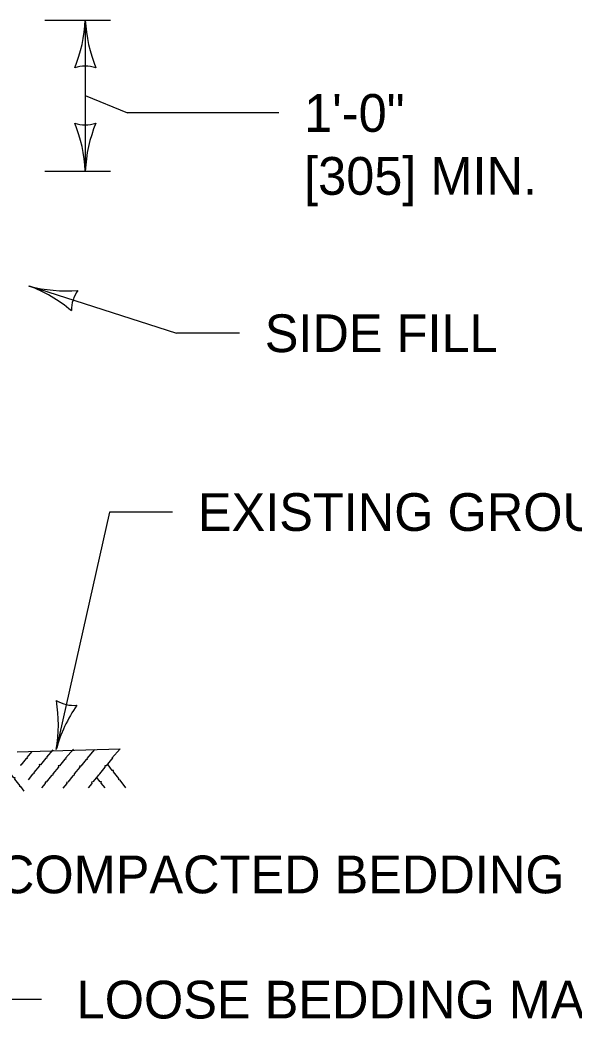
# Model space of a CAD drawing. Extents: x 49991.4 to 50021, y 49987.6 to 50011.4.
# Drawn here: x 50005.577 to 50006.457, y 49992.853 to 49994.441 of the extents above; entities that cross this region are included whole.
import ezdxf

# ---------------------------------------------------------------- set-up
doc = ezdxf.new("R2010")
doc.units = 0
for name, color, linetype in [('Level 1', 7, 'Continuous'), ('Level 2', 7, 'Continuous'), ('Level 3', 7, 'Continuous')]:
    doc.layers.add(name, color=color, linetype=linetype)

msp = doc.modelspace()

# ---------------------------------------------------------------- linework, layer by layer
at = {"layer": 'Level 1'}
msp.add_line((50005.5724, 49993.2778), (50005.7362, 49993.2827), dxfattribs=at)
for points in [[(50005.5959, 49993.2783), (50005.5877, 49993.2687), (50005.5885, 49993.2671), (50005.5869, 49993.2671), (50005.5784, 49993.2566), (50005.5773, 49993.2567)], [(50005.6291, 49993.281), (50005.6191, 49993.2694), (50005.6199, 49993.2678), (50005.6183, 49993.2678), (50005.6098, 49993.2573), (50005.6077, 49993.2574), (50005.6079, 49993.2553), (50005.5991, 49993.2448), (50005.5991, 49993.2427), (50005.5972, 49993.2421), (50005.5903, 49993.2334)], [(50005.6619, 49993.2822), (50005.6492, 49993.2674), (50005.65, 49993.2658), (50005.6484, 49993.2658), (50005.6399, 49993.2554), (50005.6377, 49993.2554), (50005.638, 49993.2534), (50005.6292, 49993.2428), (50005.6292, 49993.2407), (50005.6273, 49993.2401), (50005.6189, 49993.2296), (50005.6169, 49993.2295), (50005.6173, 49993.2275), (50005.6112, 49993.2204)], [(50005.6956, 49993.2816), (50005.6833, 49993.2671), (50005.684, 49993.2655), (50005.6824, 49993.2656), (50005.6739, 49993.2551), (50005.6718, 49993.2551), (50005.672, 49993.2531), (50005.6632, 49993.2425), (50005.6632, 49993.2405), (50005.6613, 49993.2398), (50005.653, 49993.2294), (50005.651, 49993.2292), (50005.6513, 49993.2272), (50005.6453, 49993.2201)], [(50005.7362, 49993.2827), (50005.7232, 49993.2676), (50005.7239, 49993.2659), (50005.7223, 49993.266), (50005.7138, 49993.2555), (50005.7117, 49993.2555), (50005.7119, 49993.2535), (50005.7032, 49993.2429), (50005.7031, 49993.2409), (50005.7012, 49993.2402), (50005.6929, 49993.2298), (50005.6908, 49993.2297), (50005.6912, 49993.2276), (50005.6852, 49993.2205)], [(50005.5838, 49993.2152), (50005.5785, 49993.2225), (50005.5768, 49993.2221), (50005.5772, 49993.2236), (50005.5689, 49993.2343), (50005.5694, 49993.2363), (50005.5674, 49993.2366), (50005.559, 49993.2475), (50005.5571, 49993.248), (50005.5569, 49993.25), (50005.5486, 49993.2605), (50005.5489, 49993.2625), (50005.5469, 49993.2626), (50005.5374, 49993.2752)], [(50005.7455, 49993.2205), (50005.736, 49993.2329), (50005.7341, 49993.2334), (50005.7339, 49993.2353), (50005.7255, 49993.2459), (50005.7259, 49993.2478), (50005.7238, 49993.2479), (50005.716, 49993.2584)], [(50005.7122, 49993.2205), (50005.7063, 49993.228), (50005.7067, 49993.23), (50005.7046, 49993.2301), (50005.6989, 49993.2377)]]:
    msp.add_lwpolyline(points, dxfattribs=at)
at = {"layer": 'Level 3'}
for p, q in [((50005.6168, 49994.4405), (50005.7208, 49994.4405)), ((50005.6168, 49994.4405), (50005.7208, 49994.4405)), ((50005.6808, 49994.4405), (50005.6808, 49994.2005)), ((50005.6808, 49994.3205), (50005.7477, 49994.2928)), ((50005.9885, 49994.2928), (50005.7477, 49994.2928)), ((50005.6168, 49994.2005), (50005.7208, 49994.2005)), ((50005.6168, 49994.2005), (50005.7208, 49994.2005)), ((50005.5914, 49994.0179), (50005.826, 49993.9428)), ((50005.926, 49993.9428), (50005.826, 49993.9428)), ((50005.7193, 49993.6587), (50005.6345, 49993.2812)), ((50005.8193, 49993.6587), (50005.7193, 49993.6587)), ((50005.611, 49992.884), (50004.4589, 49992.884))]:
    msp.add_line(p, q, dxfattribs=at)
for centre, radius, start, end in [((50005.4587, 49994.4497), 0.2223, 337.456, 357.6395), ((50005.4587, 49994.4497), 0.2223, 337.456, 357.6395), ((50005.9136, 49994.452), 0.233, 182.8273, 202.0772), ((50005.9136, 49994.452), 0.233, 182.8273, 202.0772), ((50005.6808, 49994.3123), 0.0548, 72.1388, 107.8612), ((50005.6808, 49994.3123), 0.0548, 72.1388, 107.8612), ((50005.6808, 49994.3288), 0.0548, 252.1388, 287.8612), ((50005.4481, 49994.1891), 0.233, 2.8273, 22.0772), ((50005.6808, 49994.3288), 0.0548, 252.1388, 287.8612), ((50005.4481, 49994.1891), 0.233, 2.8273, 22.0772), ((50005.903, 49994.1914), 0.2223, 157.456, 177.6395), ((50005.903, 49994.1914), 0.2223, 157.456, 177.6395), ((50005.5149, 49993.8091), 0.2223, 49.7048, 69.8883), ((50005.6514, 49994.243), 0.233, 255.0761, 274.326), ((50005.7135, 49993.9788), 0.0548, 144.3876, 180.11), ((50005.405, 49993.321), 0.233, 350.1728, 9.4227), ((50005.6626, 49993.4063), 0.0548, 239.4843, 275.2067), ((50005.8493, 49993.2236), 0.2223, 144.8015, 164.985)]:
    msp.add_arc(centre, radius, start, end, dxfattribs=at)

# ---------------------------------------------------------------- texts
at = {"layer": 'Level 2'}
for s, p in [('1\'-0" ', (50006.0285, 49994.2628)), ('[305] MIN.', (50006.0285, 49994.1628)), ('SIDE FILL', (50005.966, 49993.9128)), ('EXISTING GROUND', (50005.8597, 49993.6287)), ('COMPACTED BEDDING MATERIAL', (50005.542, 49993.0529)), ('LOOSE BEDDING MATERIAL', (50005.6671, 49992.854))]:
    msp.add_text(s, height=0.06, dxfattribs=at).set_placement(p)

doc.saveas('drawing.dxf')
